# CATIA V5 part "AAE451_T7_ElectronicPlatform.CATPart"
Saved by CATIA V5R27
Part number: AAE451_T7_ElectronicPlatform
Material "Plastic": density 1200 kg/m3, Young's modulus 2.2e+09 Pa, Poisson ratio 0.38, thermal expansion 6.84e-05 1/K
Bounding box of the stored display mesh (mm): x -80 to 80, y -86.049 to 86.049, z -24.74 to 5.651
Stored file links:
  W:\pu.data\Desktop\Senior Design\AAE451_T7_ElectronicPlatform.CATPart
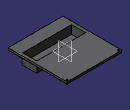
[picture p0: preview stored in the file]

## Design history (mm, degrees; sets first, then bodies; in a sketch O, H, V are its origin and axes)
Body1 (main body), material "Plastic"
  Sketch1 on xy-plane, origin (0, 0, 0), H (1, 0, 0), V (0, 1, 0)
    line L1 (-80, 86.0485) -> (80, 86.0485)
    line L2 (80, 86.0485) -> (80, -86.0485)
    line L3 (80, -86.0485) -> (-80, -86.0485)
    line L4 (-80, -86.0485) -> (-80, 86.0485)
    length L1 = 160
    length L4 = 172.097
    distance L4 O = 80
    distance L3 O = 86.0485
    horizontal: L1 H, L3 H
    vertical: L2 V, L4 V
  Pad1: profile Sketch1, direction (0, 0, 1), length 5.651
  Sketch2 on start face of Pad1, origin (0, 0, 0), H (1, 0, 0), V (0, -1, 0)
    line L1 (-72.275, 53.04) -> (72.275, 53.04)
    line L2 (72.275, 53.04) -> (72.275, 10)
    line L3 (72.275, 10) -> (-72.275, 10)
    line L4 (-72.275, 10) -> (-72.275, 53.04)
    reference projected line E1 (-80, -86.0485) -> (-80, 86.0485) from edge [start face of Pad1 | face of Pad1 from Sketch1.L4]
    length L1 = 144.55
    length L2 = 43.04
    distance L3 H = 10
    distance E1 L4 = 7.725
    horizontal: L1 H, L3 H
    vertical: L2 V, L4 V
  Pad2: profile Sketch2, direction (0, 0, -1), length 24.74
  Sketch3 on end face of Pad1, origin (0, 0, 5.651), H (1, 0, 0), V (0, 1, 0)
    line L1 (-71.275, -11) -> (71.275, -11)
    line L2 (71.275, -11) -> (71.275, -52.04)
    line L3 (71.275, -52.04) -> (-71.275, -52.04)
    line L4 (-71.275, -52.04) -> (-71.275, -11)
    reference projected line E1 (-80, 86.0485) -> (-80, -86.0485) from edge [face of Pad1 from Sketch1.L4 | end face of Pad1]
    length L1 = 142.55
    length L2 = 41.04
    distance E1 L4 = 8.725
    distance H L1 = 11
    horizontal: L1 H, L3 H
    vertical: L2 V, L4 V
  Pocket1: profile Sketch3, direction (0, 0, -1), length 24.74
  Sketch4 on end face of Pad1, origin (70.1798, 70.5285, 5.651), H (1, 0, 0), V (0, 1, 0)
    point P1 (4.8202, 10.52)
    reference projected line E1 (9.8202, 15.52) -> (-150.1798, 15.52) from edge [face of Pad1 from Sketch1.L1 | end face of Pad1]
    reference projected line E2 (9.8202, -156.577) -> (9.8202, 15.52) from edge [face of Pad1 from Sketch1.L2 | end face of Pad1]
    distance P1 E1 = 5
    distance P1 E2 = 5
  Hole1: placed by Sketch4, at (75, 81.0485, 5.651) direction (0, 0, -1), diameter 5, depth 10, V-bottom angle 120
  Sketch5 on end face of Pad1, origin (-71.8453, 80.817, 5.651), H (1, 0, 0), V (0, 1, 0)
    point P1 (-3.1547, 0.2315)
    reference projected line E1 (-8.1547, 5.2315) -> (-8.1547, -166.8655) from edge [face of Pad1 from Sketch1.L4 | end face of Pad1]
    reference projected line E2 (151.8453, 5.2315) -> (-8.1547, 5.2315) from edge [face of Pad1 from Sketch1.L1 | end face of Pad1]
    distance P1 E1 = 5
    distance P1 E2 = 5
  Hole2: placed by Sketch5, at (-75, 81.0485, 5.651) direction (0, 0, -1), diameter 5, depth 10, V-bottom angle 120
Relations
  Sketch1.distance(L4 O) = PartBody\Sketch.2\Length.5\Length PartBody\Sketch.2\Length.5\Length/2 (deactivated)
